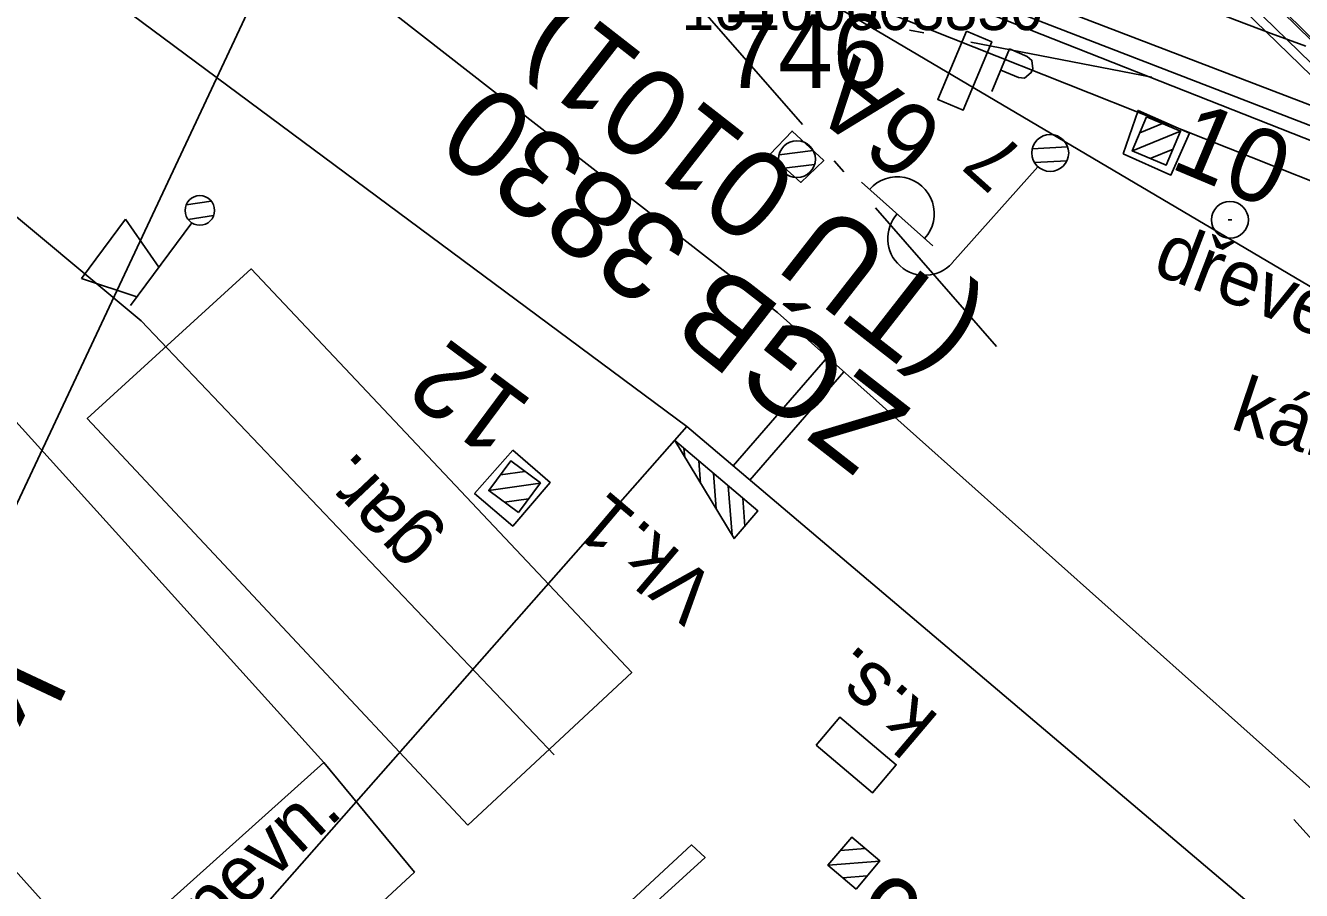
# Model space of a CAD drawing. Extents: x -800194 to -799078, y -1007177 to -1006597.
# Drawn here: x -799787.82 to -799753.2, y -1007000.4 to -1006976.93 of the extents above; entities that cross this region are included whole.
import ezdxf

# ---------------------------------------------------------------- set-up
doc = ezdxf.new("R2010")
doc.units = 0
for name, color, linetype in [('02_Osa_koleje', 7, 'Continuous'), ('_návrh', 7, 'Continuous'), ('Obvod stavby', 7, 'Continuous'), ('Vrstva 1', 7, 'Continuous'), ('Vrstva 11', 7, 'Continuous'), ('Vrstva 12', 7, 'Continuous'), ('Vrstva 16', 7, 'Continuous'), ('Vrstva 18', 7, 'Continuous'), ('Vrstva 23', 7, 'Continuous'), ('Vrstva 25', 7, 'Continuous'), ('Vrstva 3', 7, 'Continuous'), ('Vrstva 33', 7, 'Continuous'), ('Vrstva 36', 7, 'Continuous'), ('Vrstva 4', 7, 'Continuous'), ('Vrstva 5', 7, 'Continuous'), ('Vrstva 50', 7, 'Continuous'), ('Vrstva 55', 7, 'Continuous'), ('Vrstva 60', 7, 'Continuous'), ('Vrstva 63', 7, 'Continuous'), ('Vrstva 7', 7, 'Continuous')]:
    doc.layers.add(name, color=color, linetype=linetype)

msp = doc.modelspace()

# ---------------------------------------------------------------- linework, layer by layer
at = {"layer": '02_Osa_koleje'}
msp.add_lwpolyline([(-799770.682, -1006970.328), (-799769.768, -1006970.733), (-799768.852, -1006971.134), (-799767.934, -1006971.532), (-799767.016, -1006971.927), (-799766.096, -1006972.319), (-799765.175, -1006972.709), (-799764.252, -1006973.095), (-799763.329, -1006973.478), (-799762.404, -1006973.858), (-799761.478, -1006974.235), (-799760.55, -1006974.609), (-799759.621, -1006974.98), (-799758.692, -1006975.348), (-799757.761, -1006975.713), (-799756.828, -1006976.075), (-799755.895, -1006976.434), (-799754.96, -1006976.789), (-799754.025, -1006977.142), (-799753.088, -1006977.491)], dxfattribs=at)
at = {"layer": '_návrh'}
for points in [[(-799821.595, -1006948.007), (-799811.064, -1006954.324), (-799803.753, -1006958.707), (-799793.935, -1006964.581), (-799784.224, -1006971.671), (-799782.913, -1006972.63), (-799767.418, -1006984.719), (-799752.333, -1006998.173), (-799735.027, -1007015.997), (-799721.623, -1007030.81), (-799713.555, -1007039.726), (-799713.111, -1007040.218)], [(-799820.755, -1006954.001), (-799803.004, -1006964.743), (-799786.682, -1006975.322), (-799769.882, -1006987.807), (-799754.745, -1007000.643), (-799736.311, -1007017.261), (-799721.623, -1007030.81)]]:
    msp.add_lwpolyline(points, dxfattribs=at)
at = {"layer": 'Obvod stavby'}
msp.add_lwpolyline([(-799664.426, -1006999.087), (-799684.601, -1006997.477), (-799704.619, -1006994.49), (-799724.386, -1006990.14), (-799749.554, -1006982.491), (-799772.102, -1006973.528), (-799780.707, -1006969.551), (-799777.674, -1006963.242), (-799769.263, -1006967.129), (-799747.228, -1006975.889), (-799722.648, -1006983.359), (-799703.35, -1006987.606), (-799683.806, -1006990.523), (-799664.228, -1006992.091)], dxfattribs=at)
at = {"layer": 'Vrstva 1'}
msp.add_lwpolyline([(-799773.482, -1006996.72), (-799784.684, -1006984.939), (-799796.383, -1006975.181), (-799798.809, -1006973.435), (-799814.345, -1006963.355), (-799826.008, -1006956.394)], dxfattribs=at)
at = {"layer": 'Vrstva 11'}
for p, q in [((-799757.792, -1006980.327), (-799756.487, -1006979.793)), ((-799757.587, -1006979.838), (-799756.976, -1006979.588)), ((-799766.454, -1006980.322), (-799767.374, -1006980.435)), ((-799757.307, -1006980.534), (-799756.688, -1006980.28)), ((-799766.415, -1006980.695), (-799767.322, -1006980.806)), ((-799774.277, -1006989.026), (-799774.939, -1006989.123)), ((-799773.856, -1006989.342), (-799775.251, -1006989.548)), ((-799774.172, -1006989.768), (-799774.826, -1006989.864)), ((-799765.042, -1006999.255), (-799765.709, -1006999.31)), ((-799764.642, -1006999.598), (-799766.047, -1006999.714)), ((-799764.985, -1007000.003), (-799765.643, -1007000.057))]:
    msp.add_line(p, q, dxfattribs=at)
for points in [[(-799757.407, -1006979.408), (-799756.485, -1006979.794), (-799756.871, -1006980.716), (-799757.793, -1006980.33)], [(-799774.451, -1006990.143), (-799775.254, -1006989.546), (-799774.657, -1006988.743), (-799773.854, -1006989.34)], [(-799765.287, -1007000.359), (-799766.05, -1006999.712), (-799765.403, -1006998.949), (-799764.64, -1006999.596)]]:
    msp.add_lwpolyline(points, close=True, dxfattribs=at)
msp.add_circle((-799766.892, -1006980.556), 0.5, dxfattribs=at)
at = {"layer": 'Vrstva 12'}
for points in [[(-799758.044, -1006980.409), (-799757.635, -1006979.231), (-799756.238, -1006979.849), (-799756.747, -1006980.984), (-799758.044, -1006980.409)], [(-799767.624, -1006980.428), (-799767.025, -1006979.792), (-799766.166, -1006980.593), (-799766.788, -1006981.184), (-799767.624, -1006980.428)], [(-799774.6, -1006988.448), (-799773.586, -1006989.331), (-799774.604, -1006990.51), (-799775.637, -1006989.625), (-799774.6, -1006988.448)]]:
    msp.add_lwpolyline(points, dxfattribs=at)
at = {"layer": 'Vrstva 16'}
for points in [[(-799784.356, -1006949.5), (-799780.347, -1006952.62), (-799777.716, -1006954.827), (-799764.168, -1006966.436), (-799754.935, -1006975.363), (-799742.857, -1006987.188), (-799736.94, -1006992.081), (-799727.324, -1007000.028)], [(-799727.258, -1006999.988), (-799736.887, -1006992.032), (-799742.859, -1006987.132), (-799754.894, -1006975.337), (-799764.135, -1006966.374), (-799777.698, -1006954.783), (-799780.331, -1006952.581), (-799784.321, -1006949.462)], [(-799727.952, -1007000.326), (-799729.82, -1006998.717), (-799737.37, -1006992.486), (-799743.358, -1006987.594), (-799755.401, -1006975.883), (-799764.592, -1006966.926), (-799778.073, -1006955.449), (-799779.598, -1006954.142), (-799780.843, -1006953.125)], [(-799785.824, -1007002.398), (-799779.728, -1006996.929), (-799777.27, -1006999.897), (-799783.203, -1007005.389), (-799785.824, -1007002.398)]]:
    msp.add_lwpolyline(points, dxfattribs=at)
at = {"layer": 'Vrstva 18'}
for points in [[(-799737.37, -1006992.486), (-799743.358, -1006987.594), (-799755.401, -1006975.883), (-799764.592, -1006966.926), (-799778.073, -1006955.449)], [(-799729.664, -1006998.596), (-799737.245, -1006992.341), (-799743.186, -1006987.438), (-799755.222, -1006975.72), (-799764.444, -1006966.802), (-799777.959, -1006955.323)]]:
    msp.add_lwpolyline(points, dxfattribs=at)
at = {"layer": 'Vrstva 23'}
for points in [[(-799795.856, -1006979.079), (-799779.728, -1006996.929), (-799785.824, -1007002.398), (-799801.87, -1006984.513), (-799795.856, -1006979.079)], [(-799775.824, -1006998.626), (-799786.148, -1006987.593), (-799781.696, -1006983.534), (-799771.373, -1006994.479), (-799775.824, -1006998.626)], [(-799771.638, -1007000.908), (-799769.754, -1006999.159), (-799769.387, -1006999.5), (-799771.3, -1007001.249), (-799771.638, -1007000.908)]]:
    msp.add_lwpolyline(points, dxfattribs=at)
at = {"layer": 'Vrstva 25'}
for p, q in [((-799759.551, -1006980.219), (-799760.507, -1006980.274)), ((-799760.353, -1006980.759), (-799762.682, -1006983.371)), ((-799759.566, -1006980.595), (-799760.444, -1006980.645)), ((-799763.205, -1006982.905), (-799765.145, -1006981.175))]:
    msp.add_line(p, q, dxfattribs=at)
msp.add_lwpolyline([(-799766.372, -1006996.457), (-799765.725, -1006995.694), (-799764.2, -1006996.987), (-799764.847, -1006997.75), (-799766.372, -1006996.457)], dxfattribs=at)
msp.add_circle((-799760.02, -1006980.386), 0.5, dxfattribs=at)
for centre, start, end in [((-799764.167, -1006982.031), 317.5683, 138.9735), ((-799763.429, -1006982.706), 138.2709, 318.2709)]:
    msp.add_arc(centre, 1, start, end, dxfattribs=at)
at = {"layer": 'Vrstva 3'}
for p, q in [((-799769.882, -1006987.807), (-799828.64, -1007054.5)), ((-799769.958, -1006988.398), (-799769.933, -1006988.638)), ((-799769.558, -1006988.737), (-799769.507, -1006989.353)), ((-799769.157, -1006989.077), (-799769.085, -1006990.046)), ((-799768.757, -1006989.417), (-799768.653, -1006990.755)), ((-799768.357, -1006989.756), (-799768.307, -1006990.509)), ((-799767.963, -1006990.09), (-799767.967, -1006990.109)), ((-799753.41, -1006998.473), (-799752.739, -1006999.215))]:
    msp.add_line(p, q, dxfattribs=at)
msp.add_lwpolyline([(-799770.205, -1006988.188), (-799768.596, -1006990.85), (-799767.956, -1006990.096), (-799770.205, -1006988.188)], dxfattribs=at)
at = {"layer": 'Vrstva 33'}
for p, q in [((-799782.786, -1006981.691), (-799783.46, -1006981.79)), ((-799786.302, -1006983.792), (-799785.109, -1006982.186)), ((-799785.109, -1006982.186), (-799784.203, -1006983.482)), ((-799782.719, -1006982.086), (-799783.408, -1006982.187)), ((-799784.978, -1006984.526), (-799783.313, -1006982.28)), ((-799784.8, -1006984.285), (-799786.302, -1006983.792))]:
    msp.add_line(p, q, dxfattribs=at)
msp.add_circle((-799783.093, -1006981.945), 0.401, dxfattribs=at)
at = {"layer": 'Vrstva 36'}
msp.add_lwpolyline([(-799762.294, -1006977.079), (-799761.607, -1006977.367), (-799762.386, -1006979.225), (-799763.073, -1006978.937)], close=True, dxfattribs=at)
msp.add_lwpolyline([(-799761.609, -1006978.721), (-799761.124, -1006977.564), (-799760.643, -1006977.766), (-799760.518, -1006977.875), (-799760.494, -1006978.105), (-799760.537, -1006978.207), (-799760.719, -1006978.356), (-799760.882, -1006978.337), (-799761.363, -1006978.135)], dxfattribs=at)
at = {"layer": 'Vrstva 4'}
for points in [[(-799776.864, -1006969.085), (-799770.965, -1006971.646), (-799761.91, -1006975.649), (-799748.544, -1006980.777), (-799731.457, -1006986.215), (-799711.132, -1006991.054), (-799705.482, -1006992.16), (-799693.53, -1006994.084), (-799682.801, -1006995.384), (-799671.514, -1006996.319), (-799659.449, -1006996.851), (-799648.588, -1006996.949), (-799637.262, -1006996.573), (-799625.835, -1006995.773), (-799614.546, -1006994.586), (-799603.199, -1006992.945), (-799591.969, -1006990.857), (-799580.647, -1006988.335), (-799569.534, -1006985.311), (-799558.557, -1006981.947), (-799541.405, -1006975.739), (-799530.263, -1006971.071), (-799519.455, -1006966), (-799509.248, -1006960.724)], [(-799776.864, -1006969.085), (-799771.262, -1006971.982), (-799762.131, -1006976.093), (-799748.706, -1006981.286), (-799731.51, -1006986.353), (-799711.222, -1006991.459), (-799705.527, -1006992.587), (-799693.582, -1006994.543), (-799682.85, -1006995.904), (-799671.5, -1006996.805), (-799659.556, -1006997.356), (-799648.616, -1006997.341), (-799637.276, -1006997.071), (-799625.828, -1006996.297), (-799614.43, -1006995.109), (-799603.18, -1006993.475), (-799591.849, -1006991.264), (-799580.564, -1006988.698), (-799569.449, -1006985.746), (-799558.385, -1006982.386), (-799541.268, -1006976.227), (-799530.102, -1006971.505), (-799519.398, -1006966.36), (-799509.087, -1006961.127)], [(-799776.864, -1006969.085), (-799771.693, -1006972.522), (-799762.217, -1006976.394), (-799748.898, -1006981.647), (-799733.68, -1006986.66), (-799728.795, -1006987.945), (-799711.349, -1006992.599), (-799705.744, -1006994.116), (-799693.689, -1006996.09), (-799689.347, -1006996.226), (-799688.222, -1006996.296), (-799683.105, -1006997.407), (-799671.667, -1006998.275)]]:
    msp.add_lwpolyline(points, dxfattribs=at)
at = {"layer": 'Vrstva 5'}
msp.add_line((-799796.24, -1007007.322), (-799778.659, -1006969.886), dxfattribs=at)
at = {"layer": 'Vrstva 50'}
msp.add_line((-799755.194, -1006982.202), (-799755.094, -1006982.202), dxfattribs=at)
msp.add_circle((-799755.144, -1006982.202), 0.5, dxfattribs=at)
at = {"layer": 'Vrstva 55'}
msp.add_lwpolyline([(-799785.23, -1006937.71), (-799791.69, -1006959.99), (-799791.97, -1006960.97), (-799746.76, -1006987.67), (-799745.68, -1006988.03), (-799733.28, -1006992.13)], dxfattribs=at)
at = {"layer": 'Vrstva 63'}
for p, q in [((-799770.028, -1006975.851), (-799766.738, -1006979.616)), ((-799763.843, -1006977.052), (-799763.451, -1006977.128)), ((-799762.175, -1006977.376), (-799757.266, -1006978.329)), ((-799765.883, -1006980.595), (-799765.62, -1006980.896)), ((-799764.764, -1006981.875), (-799761.474, -1006985.641))]:
    msp.add_line(p, q, dxfattribs=at)
at = {"layer": 'Vrstva 7'}
for p, q in [((-799768.626, -1006988.872), (-799766.064, -1006985.927)), ((-799768.168, -1006989.26), (-799765.616, -1006986.326)), ((-799767.02, -1006987.483), (-799767.02, -1006987.483))]:
    msp.add_line(p, q, dxfattribs=at)

# ---------------------------------------------------------------- texts
at = {"layer": 'Obvod stavby'}
msp.add_text('746', height=2, rotation=360, dxfattribs=at).set_placement((-799768.895, -1006978.625))
at = {"layer": 'Vrstva 11'}
for s, rotation, p in [('6A', 142.0391, (-799762.78, -1006979.693)), ('10', 337.2647, (-799756.815, -1006980.771)), ('12', 143.3819, (-799773.999, -1006987.156)), ('6', 139.7024, (-799763.268, -1007000.735))]:
    msp.add_text(s, height=2, rotation=rotation, dxfattribs=at).set_placement(p)
at = {"layer": 'Vrstva 16'}
msp.add_text('zpevn.', height=1.5, rotation=42.7895, dxfattribs=at).set_placement((-799783.502, -1007002.329))
at = {"layer": 'Vrstva 23'}
msp.add_text('gar.', height=1.5, rotation=133.3248, dxfattribs=at).set_placement((-799776.592, -1006990.935))
at = {"layer": 'Vrstva 25'}
for s, rotation, p in [('7', 138.2709, (-799760.637, -1006980.425)), ('k.s.', 139.7024, (-799762.993, -1006995.696))]:
    msp.add_text(s, height=1.5, rotation=rotation, dxfattribs=at).set_placement(p)
at = {"layer": 'Vrstva 3'}
msp.add_text('Vk.1', height=1.5, rotation=139.7024, dxfattribs=at).set_placement((-799768.972, -1006992.12))
at = {"layer": 'Vrstva 5'}
msp.add_text('km 204,169', height=2.5, rotation=244.8436, dxfattribs=at).set_placement((-799789.022, -1006993.664))
at = {"layer": 'Vrstva 50'}
for s, rotation, p in [('dřevěné kůly', 339.0461, (-799757.288, -1006983.641)), ('kámen M2', 341.4135, (-799755.173, -1006987.846))]:
    msp.add_text(s, height=1.5, rotation=rotation, dxfattribs=at).set_placement(p)
at = {"layer": 'Vrstva 60'}
msp.add_text('10100003830', height=1.2, dxfattribs=at).set_placement((-799770.028, -1006977.051))
at = {"layer": 'Vrstva 63'}
for s, p in [('(TÚ 0101)', (-799761.816, -1006984.928)), ('ZGB 3830', (-799763.727, -1006987.377))]:
    msp.add_text(s, height=2.4, rotation=142.0391, dxfattribs=at).set_placement(p)

doc.saveas('drawing.dxf')
